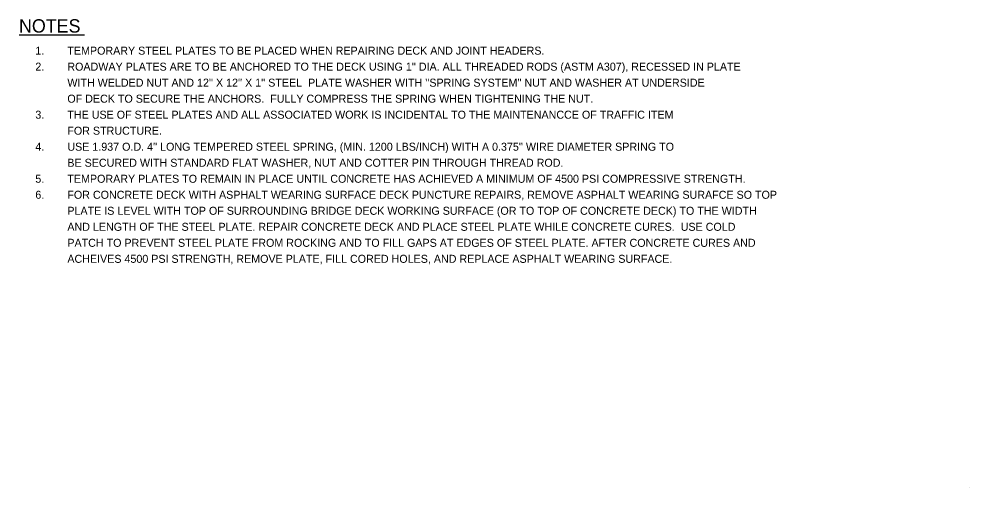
# Model space of a CAD drawing. Extents: x 12.49 to 19.62, y 5.98 to 15.32.
# Drawn here: x 12.49 to 19.62, y 5.98 to 9.5 of the extents above; entities that cross this region are included whole.
import ezdxf

# ---------------------------------------------------------------- set-up
doc = ezdxf.new("R2010")
doc.units = 0
doc.layers.add('DETL-NOTE', color=7, linetype='Continuous')
doc.layers.add('TTLB-TEXT', color=7, linetype='Continuous')

msp = doc.modelspace()

# ---------------------------------------------------------------- linework, layer by layer
at = {"layer": 'DETL-NOTE'}
msp.add_line((12.494, 9.38), (12.9849, 9.38), dxfattribs=at)
at = {"layer": 'TTLB-TEXT'}
msp.add_line((19.6208, 5.9844), (19.6208, 5.9844), dxfattribs=at)

# ---------------------------------------------------------------- texts
at = {"layer": 'DETL-NOTE'}
for s, height, p in [('NOTES', 0.1, (12.494, 9.3971)), ('1.', 0.06, (12.6163, 9.2316)), ('TEMPORARY STEEL PLATES TO BE PLACED WHEN REPAIRING DECK AND JOINT HEADERS.', 0.06, (12.8563, 9.2316)), ('2.', 0.06, (12.6163, 9.1116)), ("ROADWAY PLATES ARE TO BE ANCHORED TO THE DECK USING 1'' DIA. ALL THREADED RODS (ASTM A307), RECESSED IN PLATE ", 0.06, (12.8563, 9.1116)), ("WITH WELDED NUT AND 12'' X 12'' X 1'' STEEL  PLATE WASHER WITH ''SPRING SYSTEM'' NUT AND WASHER AT UNDERSIDE ", 0.06, (12.8563, 8.9916)), ('OF DECK TO SECURE THE ANCHORS.  FULLY COMPRESS THE SPRING WHEN TIGHTENING THE NUT.  ', 0.06, (12.8563, 8.8716)), ('3.', 0.06, (12.6163, 8.7516)), ('THE USE OF STEEL PLATES AND ALL ASSOCIATED WORK IS INCIDENTAL TO THE MAINTENANCCE OF TRAFFIC ITEM ', 0.06, (12.8563, 8.7516)), ('FOR STRUCTURE.', 0.06, (12.8563, 8.6316)), ('4.', 0.06, (12.6163, 8.5116)), ("USE 1.937 O.D. 4'' LONG TEMPERED STEEL SPRING, (MIN. 1200 LBS/INCH) WITH A 0.375'' WIRE DIAMETER SPRING TO ", 0.06, (12.8563, 8.5116)), ('BE SECURED WITH STANDARD FLAT WASHER, NUT AND COTTER PIN THROUGH THREAD ROD.', 0.06, (12.8563, 8.3916)), ('5.', 0.06, (12.6163, 8.2716)), ('TEMPORARY PLATES TO REMAIN IN PLACE UNTIL CONCRETE HAS ACHIEVED A MINIMUM OF 4500 PSI COMPRESSIVE STRENGTH.', 0.06, (12.8563, 8.2716)), ('6.', 0.06, (12.6163, 8.1516)), ('FOR CONCRETE DECK WITH ASPHALT WEARING SURFACE DECK PUNCTURE REPAIRS, REMOVE ASPHALT WEARING SURAFCE SO TOP ', 0.06, (12.8563, 8.1516)), ('PLATE IS LEVEL WITH TOP OF SURROUNDING BRIDGE DECK WORKING SURFACE (OR TO TOP OF CONCRETE DECK) TO THE WIDTH ', 0.06, (12.8563, 8.0316)), ('AND LENGTH OF THE STEEL PLATE. REPAIR CONCRETE DECK AND PLACE STEEL PLATE WHILE CONCRETE CURES.  USE COLD ', 0.06, (12.8563, 7.9116)), ('PATCH TO PREVENT STEEL PLATE FROM ROCKING AND TO FILL GAPS AT EDGES OF STEEL PLATE. AFTER CONCRETE CURES AND ', 0.06, (12.8563, 7.7916)), ('ACHEIVES 4500 PSI STRENGTH, REMOVE PLATE, FILL CORED HOLES, AND REPLACE ASPHALT WEARING SURFACE.', 0.06, (12.8563, 7.6716))]:
    msp.add_text(s, height=height, dxfattribs=at).set_placement(p)

doc.saveas('drawing.dxf')
